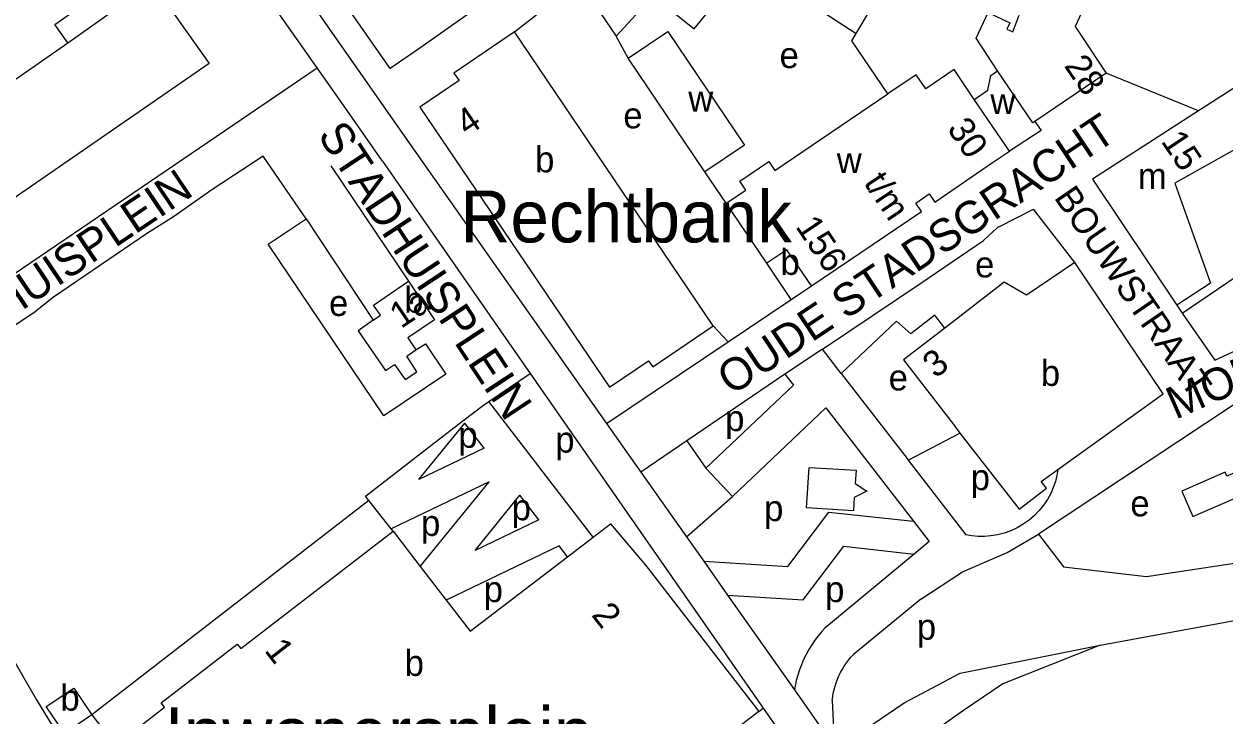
# Model space of a CAD drawing. Extents: x 160673 to 161924, y 382258 to 384145.
# Drawn here: x 161447.5 to 161632.6, y 382888.8 to 382995.5 of the extents above; entities that cross this region are included whole.
import ezdxf

# ---------------------------------------------------------------- set-up
doc = ezdxf.new("R2010")
doc.units = 0
for name, color, linetype in [('BLT_Basislijn', 7, 'Continuous'), ('BLT_Bebouwing', 7, 'Continuous'), ('BLT_Bebouwing_beschrifting', 7, 'Continuous'), ('BLT_Centroide', 7, 'Continuous'), ('BLT_Huisnummer', 7, 'Continuous'), ('BLT_Huisnummer_reeks', 7, 'Continuous'), ('BLT_Onderdoorgang_en_onderverdeling', 7, 'Continuous'), ('BLT_Onderverdeling_panden', 7, 'Continuous'), ('BLT_Straatnaam', 7, 'Continuous'), ('BLT_Straatnaam_hoofdweg', 7, 'Continuous'), ('BLT_Straatnaam_verkleind', 7, 'Continuous'), ('BLT_Vlakafsluiter', 7, 'Continuous')]:
    doc.layers.add(name, color=color, linetype=linetype)

msp = doc.modelspace()

# ---------------------------------------------------------------- linework, layer by layer
at = {"layer": 'BLT_Basislijn'}
for p, q in [((161492.74, 382988.68), (161432.9, 383074.26)), ((161523.19, 382994.25), (161533.13, 383002.07)), ((161533.13, 383002.07), (161538.86, 382993.57)), ((161538.86, 382993.57), (161544.6, 382999.82)), ((161540.74, 382990.2), (161538.86, 382993.57)), ((161420.08, 382939.26), (161492.74, 382988.68)), ((161496.63, 382983.13), (161492.74, 382988.68)), ((161502.81, 382974.3), (161496.63, 382983.13)), ((161507, 382977.03), (161537.4, 382933.81)), ((161502.81, 382974.3), (161525.62, 382941.5)), ((161555.85, 382967.79), (161552.57, 382972.65)), ((161597.89, 382964.17), (161603.24, 382966.87)), ((161609.62, 382958.62), (161603.24, 382966.87)), ((161485.19, 382961.47), (161491.05, 382965.38)), ((161491.05, 382965.38), (161501.4, 382949.72)), ((161595.63, 382962.13), (161597.66, 382964.01)), ((161503.01, 382934.97), (161485.19, 382961.47)), ((161585.85, 382955.46), (161595.52, 382962.03)), ((161570.7, 382945.26), (161585.85, 382955.45)), ((161556.14, 382946.38), (161565.87, 382952.92)), ((161626.19, 382950.83), (161631.24, 382943.54)), ((161553.84, 382948.89), (161556.14, 382946.38)), ((161631.24, 382943.54), (161640.54, 382947.93)), ((161507.98, 382945.14), (161509.43, 382946.11)), ((161509.43, 382946.11), (161512.58, 382941.41)), ((161537.4, 382933.81), (161556.14, 382946.38)), ((161570.7, 382945.26), (161564.91, 382941.38)), ((161573.58, 382941.53), (161570.7, 382945.26)), ((161512.58, 382941.41), (161503.01, 382934.97)), ((161519.24, 382937.19), (161525.62, 382941.5)), ((161525.62, 382941.5), (161561.52, 382889.86)), ((161564.91, 382941.38), (161549.79, 382931.12)), ((161564.91, 382941.38), (161566.22, 382939.72)), ((161566.22, 382939.72), (161552.69, 382926.88)), ((161535.31, 382916.25), (161519.24, 382937.19)), ((161571.23, 382936.21), (161556.83, 382922.53)), ((161571.23, 382936.21), (161584.73, 382918.69)), ((161577.51, 382936.44), (161583.75, 382928.37)), ((161634.03, 382936.61), (161604.03, 382916.71)), ((161518.48, 382929.97), (161515.5, 382933.85)), ((161537.4, 382933.81), (161542.69, 382926.3)), ((161549.79, 382931.12), (161542.69, 382926.3)), ((161549.79, 382931.12), (161552.69, 382926.88)), ((161583.93, 382928.14), (161592.81, 382916.61)), ((161542.69, 382926.3), (161549.73, 382916.28)), ((161556.83, 382922.53), (161552.69, 382926.88)), ((161568.22, 382920.79), (161568.62, 382927.02)), ((161568.62, 382927.02), (161575.87, 382926.57)), ((161575.87, 382926.57), (161575.73, 382924.52)), ((161519.28, 382924.8), (161504.16, 382917.52)), ((161508.65, 382911.71), (161519.28, 382924.8)), ((161575.73, 382924.52), (161577.52, 382923.33)), ((161526.94, 382918.93), (161524.03, 382922.73)), ((161549.73, 382916.28), (161556.83, 382922.53)), ((161577.52, 382923.33), (161575.58, 382922.39)), ((161500.7, 382921.91), (161457.98, 382888.8)), ((161504.16, 382917.52), (161500.7, 382921.91)), ((161575.48, 382920.31), (161568.22, 382920.79)), ((161575.58, 382922.39), (161575.48, 382920.31)), ((161504.44, 382917.17), (161504.16, 382917.52)), ((161584.73, 382918.69), (161587.14, 382915.55)), ((161549.73, 382916.28), (161552.38, 382912.52)), ((161587.14, 382915.55), (161584.85, 382913.64)), ((161604.03, 382916.71), (161607.9, 382911.66)), ((161530.05, 382914.88), (161512.66, 382906.51)), ((161531.34, 382913.21), (161530.05, 382914.88)), ((161584.85, 382913.64), (161571.06, 382902.18)), ((161552.38, 382912.52), (161556.06, 382907.28)), ((161556.06, 382907.28), (161565.48, 382893.9)), ((161585.87, 382906.69), (161575.47, 382898.11)), ((161613.51, 382899.59), (161640.65, 382904.53)), ((161565.48, 382893.9), (161566.37, 382892.67)), ((161566.37, 382892.67), (161572.53, 382883.88)), ((161572.2, 382891.02), (161572.53, 382883.88)), ((161560.86, 382889.34), (161561.52, 382889.86)), ((161561.52, 382889.86), (161564.04, 382886.25))]:
    msp.add_line(p, q, dxfattribs=at)
for points in [[(161465.72, 383037.79), (161466.12, 383035.53), (161507, 382977.03)], [(161454.27, 382992.55), (161467.31, 383001.83), (161476.08, 382989.35), (161436.33, 382961.95)], [(161580.77, 382984.66), (161575.23, 382992.87), (161575.89, 382993.97)], [(161484.4, 382975.08), (161476.64, 382969.98), (161470.56, 382965.68), (161466.56, 382963.16), (161452.07, 382953.28), (161449.02, 382950.87), (161439.55, 382944.66)], [(161491.05, 382965.38), (161484.4, 382975.08)], [(161494.86, 382973.54), (161506.85, 382955.78)], [(161589.56, 382948.53), (161588.05, 382950.51), (161584.32, 382947.61), (161582.12, 382949.61), (161573.58, 382941.53)], [(161573.58, 382941.53), (161577.51, 382936.44)], [(161515.23, 382934.2), (161518.39, 382936.61), (161519.24, 382937.19)], [(161500.7, 382921.91), (161500.18, 382922.55), (161510.46, 382930.55), (161515.23, 382934.2)], [(161518.48, 382929.97), (161508.41, 382925.12), (161515.5, 382933.85)], [(161583.93, 382928.14), (161591.9, 382932.3)], [(161583.75, 382928.37), (161583.93, 382928.14)], [(161607.02, 382926.7), (161606.86, 382925.78), (161606.63, 382924.85), (161606.3, 382923.91), (161605.9, 382922.98), (161605.4, 382922.07), (161604.81, 382921.2), (161604.14, 382920.36), (161603.38, 382919.59), (161602.56, 382918.88), (161601.67, 382918.24), (161600.72, 382917.7), (161599.74, 382917.24), (161598.73, 382916.88), (161597.71, 382916.61), (161596.69, 382916.44), (161595.68, 382916.36), (161594.69, 382916.37), (161593.73, 382916.45), (161592.81, 382916.61)], [(161526.94, 382918.93), (161517.11, 382914.2), (161524.03, 382922.73)], [(161552.38, 382912.52), (161565.35, 382911.71), (161571.69, 382920.11), (161584.73, 382918.69)], [(161607.9, 382911.66), (161620.7, 382910.15), (161635.24, 382912.37), (161658.42, 382917.15), (161658.7, 382919.84)], [(161585.87, 382906.69), (161592.3, 382910.91), (161599.17, 382913.89), (161604.03, 382916.71)], [(161556.06, 382907.28), (161567.72, 382906.55), (161573.97, 382914.83), (161584.85, 382913.64)], [(161439.64, 382908.09), (161449.44, 382891.13), (161461.28, 382871.73), (161473.12, 382851.91)], [(161571.06, 382902.18), (161570.58, 382901.66), (161570.04, 382901.01), (161569.52, 382900.33), (161569.03, 382899.62), (161568.58, 382898.89), (161568.17, 382898.13), (161567.79, 382897.36), (161567.44, 382896.56), (161567.14, 382895.76), (161566.88, 382894.94), (161566.65, 382894.11), (161566.47, 382893.27), (161566.37, 382892.67)], [(161613.51, 382899.59), (161598.5, 382893.6), (161592.45, 382889.51), (161580.89, 382881.32), (161568.45, 382871.7), (161552.84, 382858.82), (161542.24, 382849.33)], [(161572.53, 382883.88), (161575.89, 382885.63), (161583.3, 382890.69), (161591.95, 382895.26), (161613.51, 382899.59)], [(161572.2, 382891.02), (161572.27, 382891.58), (161572.36, 382892.14), (161572.48, 382892.69), (161572.63, 382893.24), (161572.81, 382893.78), (161573.01, 382894.32), (161573.24, 382894.85), (161573.49, 382895.36), (161573.77, 382895.86), (161574.06, 382896.35), (161574.39, 382896.82), (161574.73, 382897.27), (161575.09, 382897.7), (161575.47, 382898.11)], [(161457.98, 382888.8), (161468.58, 382875.07), (161472.54, 382869.56), (161492.83, 382843.59)]]:
    msp.add_lwpolyline(points, dxfattribs=at)
for centre, start, end in [((161598.34, 382963.27), 116.8707, 132.7995), ((161594.95, 382962.86), 304.2457, 312.7995), ((161585.29, 382956.28), 303.9446, 304.2457)]:
    msp.add_arc(centre, 1, start, end, dxfattribs=at)
at = {"layer": 'BLT_Bebouwing'}
for p, q in [((161444.45, 382985.71), (161454.27, 382992.55)), ((161552.57, 382972.65), (161540.74, 382990.2)), ((161614.46, 382987.86), (161603.46, 382980.43)), ((161562.09, 382958.52), (161555.85, 382967.79)), ((161565.87, 382952.92), (161562.09, 382958.52)), ((161565.87, 382952.92), (161569, 382955.04)), ((161501.4, 382949.72), (161502.49, 382950.49)), ((161589.56, 382948.53), (161583.18, 382943.6)), ((161506.71, 382947.01), (161507.98, 382945.14)), ((161590.94, 382933.56), (161591.9, 382932.3)), ((161504.44, 382917.17), (161508.65, 382911.71)), ((161535.31, 382916.25), (161537.97, 382918.29)), ((161531.34, 382913.21), (161535.31, 382916.25)), ((161516.36, 382901.72), (161531.34, 382913.21)), ((161508.65, 382911.71), (161512.66, 382906.51)), ((161512.66, 382906.51), (161516.36, 382901.72))]:
    msp.add_line(p, q, dxfattribs=at)
for points in [[(161454.27, 382992.55), (161452.26, 382995.4), (161454.69, 382997.1), (161452.69, 383000), (161431.98, 383029.56), (161430.49, 383028.52)], [(161609.62, 383013.96), (161616.93, 383010.52), (161611.96, 383000), (161609.66, 382995.06), (161614.46, 382987.86)], [(161544.6, 382999.82), (161550.89, 382994.7), (161559.18, 383004.89), (161575.89, 382993.97)], [(161519.6, 382999.55), (161508.6, 382991.72), (161504.01, 382988.58), (161494.96, 383001.63)], [(161575.89, 382993.97), (161580.33, 383001.45)], [(161597.71, 382988.24), (161594.39, 382993.28), (161596.24, 382997.23), (161599.6, 382995.65), (161599.14, 382994.67), (161600.06, 382994.24), (161601.05, 382996.81)], [(161523.19, 382994.25), (161513.85, 382987.89), (161514.64, 382986.74), (161508.56, 382982.6), (161537.86, 382939.38), (161543.88, 382943.44), (161544.5, 382942.53), (161553.84, 382948.89)], [(161553.84, 382948.89), (161523.19, 382994.25)], [(161540.74, 382990.2), (161546.86, 382994.31), (161558.68, 382976.76), (161552.57, 382972.65)], [(161594.11, 382983.82), (161591, 382988.41), (161586.63, 382985.45), (161585.15, 382987.63), (161580.77, 382984.66)], [(161594.11, 382983.82), (161596.21, 382985.25), (161596.65, 382987.52), (161597.71, 382988.24)], [(161646.27, 382973.79), (161642.96, 382980.6), (161637.86, 382987.9), (161628.7, 382982.03)], [(161555.85, 382967.79), (161558.87, 382969.83), (161557.96, 382971.18), (161562.44, 382974.21), (161563.35, 382972.86), (161580.77, 382984.66)], [(161628.7, 382982.03), (161612.35, 382971.49), (161625.35, 382952.08)], [(161603.46, 382980.43), (161604.42, 382979.02), (161599.53, 382975.81)], [(161569, 382955.04), (161572.81, 382957.61), (161585.96, 382966.52), (161585.08, 382967.82), (161587.16, 382969.22), (161588.04, 382967.93), (161596.91, 382974.08), (161599.53, 382975.81)], [(161609.62, 382958.62), (161602.19, 382953.62), (161598.74, 382955.62), (161589.56, 382948.53)], [(161623.27, 382938.39), (161609.62, 382958.62)], [(161626.19, 382950.83), (161638.7, 382959.29), (161643.01, 382949.05)], [(161502.49, 382950.49), (161501.43, 382952.07), (161506.85, 382955.78)], [(161506.85, 382955.78), (161510.86, 382949.81), (161506.71, 382947.01)], [(161625.35, 382952.08), (161626.19, 382950.83)], [(161501.4, 382949.72), (161499.08, 382948.11), (161503.26, 382941.95), (161504.68, 382942.91), (161506.3, 382940.57), (161508.14, 382941.77), (161506.55, 382944.18), (161507.98, 382945.14)], [(161583.18, 382943.6), (161590.94, 382933.56)], [(161607.02, 382926.7), (161623.27, 382938.39)], [(161591.9, 382932.3), (161601.04, 382920.56), (161605.23, 382923.82), (161604.44, 382924.84), (161607.02, 382926.7)], [(161636.38, 382927.12), (161633.07, 382925.66), (161632.79, 382926.29), (161626.13, 382923.36), (161627.85, 382919.44), (161633.98, 382922.12), (161658.7, 382919.84)], [(161544.88, 382878.89), (161541.31, 382883.51), (161504.06, 382854.75), (161495.3, 382847.99), (161465.24, 382886.91), (161469.19, 382889.99), (161468.67, 382890.65), (161480.42, 382899.71), (161480.96, 382899.05), (161504.44, 382917.17)], [(161537.97, 382918.29), (161543.46, 382911.87), (161560.86, 382889.34)], [(161450.95, 382890.11), (161455.18, 382892.96), (161457.98, 382888.8)], [(161457.98, 382888.8), (161453.75, 382885.96), (161450.95, 382890.11)], [(161560.86, 382889.34), (161558.19, 382887.28)]]:
    msp.add_lwpolyline(points, dxfattribs=at)
at = {"layer": 'BLT_Onderdoorgang_en_onderverdeling'}
for points in [[(161603.46, 382980.43), (161603.12, 382980.2), (161597.71, 382988.24)], [(161599.53, 382975.81), (161594.11, 382983.82)]]:
    msp.add_lwpolyline(points, dxfattribs=at)
at = {"layer": 'BLT_Onderverdeling_panden'}
for points in [[(161639.56, 382970.58), (161636.89, 382977.55), (161625.03, 382970.88), (161630.57, 382955.43), (161625.35, 382952.08)], [(161569, 382955.04), (161565.17, 382960.6), (161562.09, 382958.52)]]:
    msp.add_lwpolyline(points, dxfattribs=at)
at = {"layer": 'BLT_Vlakafsluiter'}
msp.add_line((161628.7, 382982.03), (161614.46, 382987.86), dxfattribs=at)

# ---------------------------------------------------------------- texts
at = {"layer": 'BLT_Bebouwing_beschrifting'}
for s, p in [('Rechtbank', (161514.83, 382961.74)), ('Inwonersplein', (161469.19, 382881.99))]:
    msp.add_text(s, height=8, rotation=0.0003, dxfattribs=at).set_placement(p)
at = {"layer": 'BLT_Centroide'}
for s, p in [('e', (161564.07, 382988.65)), ('w', (161549.99, 382981.95)), ('w', (161596.59, 382981.54)), ('e', (161539.97, 382979.35)), ('b', (161526.36, 382972.56)), ('w', (161572.9, 382972.44)), ('m', (161619.35, 382970)), ('b', (161564.21, 382956.73)), ('e', (161594.23, 382956.34)), ('b', (161506.17, 382950.89)), ('e', (161494.57, 382950.39)), ('b', (161604.38, 382939.59)), ('e', (161580.9, 382938.89)), ('p', (161555.68, 382932.61)), ('p', (161514.52, 382930.04)), ('p', (161529.47, 382929.3)), ('p', (161593.56, 382923.5)), ('e', (161618.19, 382919.46)), ('p', (161522.75, 382918.85)), ('p', (161561.69, 382918.72)), ('p', (161508.77, 382916.43)), ('p', (161518.43, 382906.22)), ('p', (161571.1, 382906.21)), ('p', (161585.25, 382900.41)), ('b', (161506.24, 382894.83)), ('b', (161453.13, 382889.47))]:
    msp.add_text(s, height=4, dxfattribs=at).set_placement(p)
at = {"layer": 'BLT_Huisnummer'}
for s, rotation, p in [('4', 34.2565, (161515.9, 382978.05)), ('1a', 34.0234, (161505.68, 382948.35)), ('3', 37.3959, (161588.12, 382940.65))]:
    msp.add_text(s, height=4, rotation=rotation, dxfattribs=at).set_placement(p)
at = {"layer": 'BLT_Huisnummer_reeks'}
for s, rotation, p in [('28', 304.1119, (161607.88, 382989)), ('30', 303.9419, (161589.82, 382979.3)), ('15', 303.8159, (161622.83, 382977.35)), ('t/m', 303.9419, (161576.96, 382970.94)), ('156', 303.9419, (161566.43, 382964.19)), ('2', 307.9085, (161534.94, 382904.21)), ('1', 307.8092, (161484.49, 382898.73))]:
    msp.add_text(s, height=4, rotation=rotation, dxfattribs=at).set_placement(p)
at = {"layer": 'BLT_Straatnaam'}
for s, rotation, p in [('OUDE STADSGRACHT', 33.6742, (161556.67, 382938.02)), ('STADHUISPLEIN', 303.4052, (161492.71, 382978.27)), ('STADHUISPLEIN', 33.9383, (161429.83, 382939.49)), ('MOLENSTRAAT', 23.6553, (161625.15, 382934.35))]:
    msp.add_text(s, height=5, rotation=rotation, dxfattribs=at).set_placement(p)
at = {"layer": 'BLT_Straatnaam_hoofdweg'}
msp.add_text('STADHUISPLEIN', height=8, rotation=301.3164, dxfattribs=at).set_placement((161415.36, 382920.7))
at = {"layer": 'BLT_Straatnaam_verkleind'}
msp.add_text('BOUWSTRAAT', height=4, rotation=304.4168, dxfattribs=at).set_placement((161606.32, 382968.67))

doc.saveas('drawing.dxf')
